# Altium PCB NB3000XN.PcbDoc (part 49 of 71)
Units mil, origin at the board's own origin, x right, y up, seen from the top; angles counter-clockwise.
Board outline 9527.56 x 6929.77 mil, 6 copper layers (Top Layer, GND+SHIELD, MidLayer1, MidLayer2, P2 - 3V3+5V0, Bottom Layer), stack 62.375 mil thick; 832 components, 1027 nets, 4655 pads, 4981 vias.
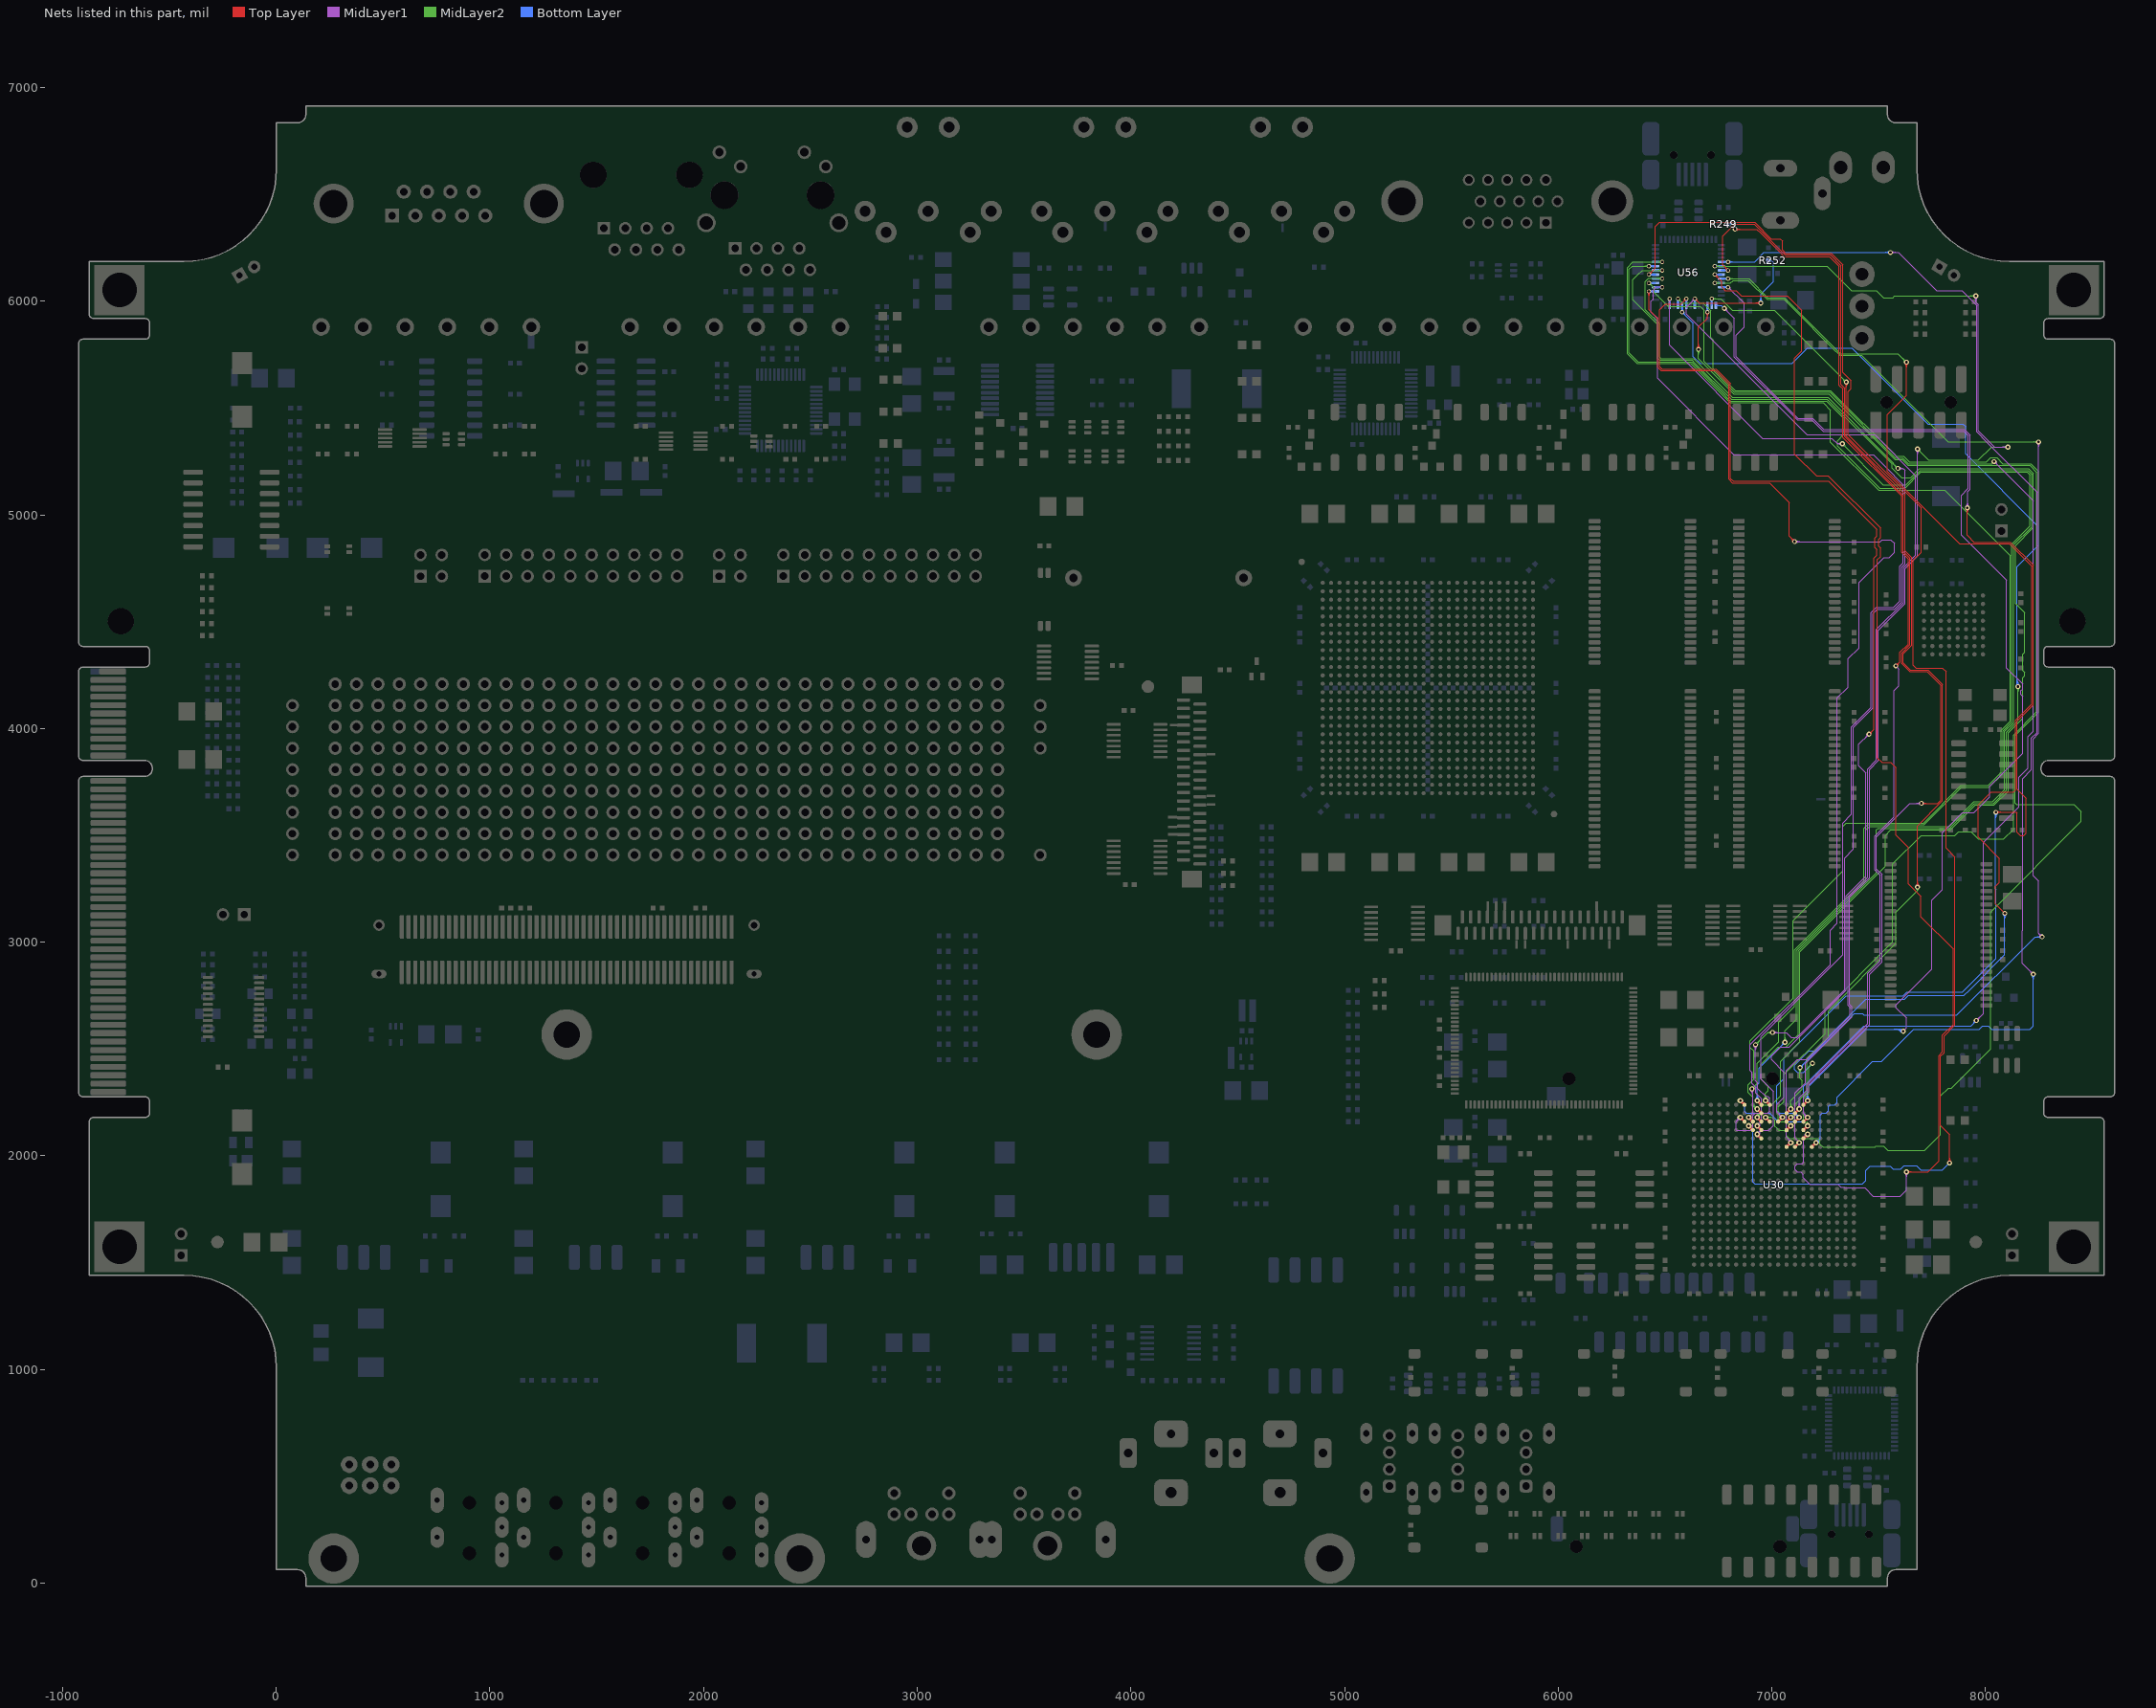
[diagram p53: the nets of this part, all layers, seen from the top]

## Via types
v1: diameter 23, hole 11.81, Top Layer to Bottom Layer, 3672 vias
v2: diameter 26, hole 11.81, Top Layer to Bottom Layer, 461 vias
v3: diameter 19, hole 11.81, Top Layer to Bottom Layer, tented both sides, 396 vias
v4: diameter 23.62, hole 11.81, Top Layer to Bottom Layer, 288 vias
v5: diameter 20, hole 11.81, Top Layer to Bottom Layer, 91 vias
v6: diameter 23, hole 11.81, Top Layer to Bottom Layer, tented both sides, 50 vias
v7: diameter 31, hole 11.81, Top Layer to Bottom Layer, 15 vias
v8: diameter 27.56, hole 11.81, Top Layer to Bottom Layer, tented both sides, 4 vias
v9: diameter 29, hole 11.81, Top Layer to Bottom Layer, 3 vias
v10: diameter 21, hole 11.81, Top Layer to Bottom Layer, 1 vias

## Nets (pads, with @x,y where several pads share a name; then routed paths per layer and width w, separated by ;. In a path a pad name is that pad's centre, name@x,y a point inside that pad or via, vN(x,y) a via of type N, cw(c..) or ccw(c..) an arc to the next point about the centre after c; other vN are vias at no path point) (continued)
HOST_USB.D1: U30.F6 U56.19 | length 6639.8
  Top Layer w8: U30.F6@7187.17,2042.17 v2(7206.85,2061.85) ; U30.F6@7187.17,2048.01 ccw(c7187.17,2062.11) 7197.14,2052.14 ccw(c7207.11,2042.17) U30.F6@7193.01,2042.17 ; v2@7197.85,2061.85 cw(c7176.12,2061.85) 7191.49,2046.49 cw(c7206.85,2031.12) v2@7206.85,2052.85
  MidLayer1 w4: v1(7554.86,6228.37) 7592.21,6228.37 7770.54,6050.04 7889.61,6050.04 7958.81,5980.84 7958.81,5388.73 8004.44,5343.11 8240.52,5107.02 8240.52,3980.73 8215.19,3955.39 8215.19,3808.37 8173.52,3766.71 8173.52,3055 ; v1@7558.75,6224.49 cw(c7568.14,6215.1) 7568.14,6228.37 cw(c7568.14,6241.65) v1@7558.75,6232.26 ; v1@7561.57,6221.66 cw(c7577.79,6205.44) 7577.79,6228.37 cw(c7577.79,6251.31) v1@7561.57,6235.09 ; 8175,3055 8173.19,3053.19 8173.19,2900.37 v1(8223.52,2850.04) ; v1@8214.02,2850.04 ccw(c8191.09,2850.04) 8207.31,2866.26 ccw(c8223.52,2882.48) v1@8223.52,2859.54 ; v1@8218.02,2850.04 ccw(c8204.75,2850.04) 8214.14,2859.43 ccw(c8223.52,2868.82) v1@8223.52,2855.54
  Bottom Layer w4: v5(6795.66,6184.21) 6919.36,6184.21 6963.52,6228.37 v1(7554.86,6228.37) ; v5@6801.32,6178.56 cw(c6814.97,6164.9) 6814.97,6184.21 cw(c6814.98,6203.53) v5@6801.32,6189.87 ; v2(7206.85,2061.85) 7206.85,2069.37 7214.38,2069.37 7227.19,2082.19 7227.19,2191.71 7235.52,2200.04 7254.19,2200.04 7265.52,2211.37 7265.52,2233.37 7271.19,2239.04 7293.86,2239.04 7304.86,2250.04 7304.86,2275.04 7471.52,2441.71 7514.52,2441.71 7664.52,2591.71 7969.52,2591.71 7986.19,2608.37 8012.86,2608.37 8029.52,2591.71 8206.86,2591.71 8223.52,2608.37 v1(8223.52,2850.04) ; v2@7206.85,2068.85 ccw(c7206.85,2085.75) 7218.8,2073.8 ; v2@7206.85,2072.85 ccw(c7206.85,2099.41) 7225.63,2080.63 ccw(c7244.41,2061.85) v2@7217.85,2061.85 ; v2@7213.85,2061.85 cw(c7230.75,2061.85) 7218.8,2073.8 ; v1@7548.14,6221.66 ccw(c7531.92,6205.44) 7531.92,6228.37 ccw(c7531.92,6251.31) v1@7548.14,6235.09 ; v1@7550.97,6224.49 ccw(c7541.58,6215.1) 7541.58,6228.37 ccw(c7541.58,6241.65) v1@7550.97,6232.26 ; v1@8216.81,2843.32 cw(c8200.59,2827.11) 8223.52,2827.11 cw(c8246.46,2827.11) v1@8230.24,2843.32 ; v1@8219.64,2846.15 cw(c8210.25,2836.76) 8223.52,2836.76 cw(c8236.8,2836.76) v1@8227.41,2846.15
  Bottom Layer w8: U56.19@6764.33,6184.21 v5(6795.66,6184.21) ; v5@6791.42,6179.97 ccw(c6781.18,6169.73) 6781.18,6184.21 ccw(c6781.17,6198.7) v5@6791.42,6188.46
HOST_USB.D2: U30.H6 U56.20 | length 6594.3
  Top Layer w8: U30.H6@7108.43,2042.17 v2(7128.11,2061.85) ; U30.H6@7108.43,2048.01 ccw(c7108.43,2062.11) 7118.4,2052.14 ccw(c7128.37,2042.17) U30.H6@7114.27,2042.17 ; v2@7119.11,2061.85 cw(c7097.38,2061.85) 7112.75,2046.49 cw(c7128.11,2031.12) v2@7128.11,2052.85
  MidLayer1 w4: v2(7128.11,2061.85) 7128.11,2058.37 7131.86,2058.37 7131.86,2060.37 7108.86,2083.37 7108.86,2293.71 7156.86,2341.71 7156.86,2433.37 7374.34,2650.86 7374.34,2698.16 7364.52,2707.98 7364.52,3210.08 7456.86,3302.41 7456.86,3808.37 7498.52,3850.04 7498.52,4459.84 7623.86,4585.17 7623.86,4749.77 7681.86,4807.77 v1(7681.86,5308.37) ; v1@7675.14,5301.66 cw(c7658.92,5285.44) 7681.86,5285.44 cw(c7704.79,5285.44) v1@7688.57,5301.66 ; v1@7677.97,5304.49 cw(c7668.58,5295.1) 7681.86,5295.1 cw(c7695.14,5295.1) v1@7685.75,5304.49 ; v4@7948.06,6018.06 cw(c7931.31,6001.31) 7955,6001.31 cw(c7978.69,6001.31) v4@7961.94,6018.06 ; v4@7950.89,6020.89 cw(c7940.97,6010.97) 7955,6010.97 cw(c7969.03,6010.97) v4@7959.11,6020.89 ; v4(7955,6025) 7955,5995.96 7966.81,5984.15 7966.81,5393.19 8042.19,5317.81 v4(8105,5317.81) ; v4@8098.06,5310.87 ccw(c8081.31,5294.13) 8081.31,5317.81 ccw(c8081.31,5341.5) v4@8098.06,5324.75 ; v4@8100.89,5313.7 ccw(c8090.97,5303.78) 8090.97,5317.81 ccw(c8090.97,5331.84) v4@8100.89,5321.92
  MidLayer2 w4: v5(6733,6164.53) 7259.04,6164.53 7373.52,6050.04 7490.19,6050.04 7523.04,6017.19 7567.19,6017.19 7575,6025 v4(7955,6025) ; v5@6738.66,6158.87 cw(c6752.31,6145.21) 6752.31,6164.53 cw(c6752.31,6183.84) v5@6738.66,6170.18 ; v1@7681.86,5298.87 cw(c7681.86,5275.94) 7698.07,5292.16 cw(c7714.29,5308.37) v1@7691.36,5308.37 ; v1@7681.86,5302.87 cw(c7681.86,5289.6) 7691.25,5298.99 cw(c7700.64,5308.37) v1@7687.36,5308.37 ; v1(7681.86,5308.37) 7734.23,5256 7966,5256 8027.81,5317.81 v4(8105,5317.81) ; v4@7948.06,6018.06 ccw(c7931.31,6001.31) 7931.31,6025 ccw(c7931.31,6048.69) v4@7948.06,6031.94 ; v4@7950.89,6020.89 ccw(c7940.97,6010.97) 7940.97,6025 ccw(c7940.97,6039.03) v4@7950.89,6029.11 ; v4@8098.06,5310.87 ccw(c8081.31,5294.13) 8081.31,5317.81 ccw(c8081.31,5341.5) v4@8098.06,5324.75 ; v4@8100.89,5313.7 ccw(c8090.97,5303.78) 8090.97,5317.81 ccw(c8090.97,5331.84) v4@8100.89,5321.92
  Bottom Layer w8: v5(6733,6164.53) U56.20@6764.33,6164.53 ; v5@6737.24,6160.28 cw(c6747.49,6150.04) 6747.49,6164.53 cw(c6747.49,6179.01) v5@6737.24,6168.77
HOST_USB.D3: U30.G3 U56.21 | length 5809.5
  Top Layer w4: 6782.01,6158.5 cw(c6768.35,6144.84) v5@6787.66,6144.84 ; 6782,6158.5 ccw(c6795.66,6172.16) v5@6795.66,6152.84 ; v5(6795.66,6144.84) 6770,6170.5 6770,6304.85 6825.19,6360.04 6917.84,6360.04 7061.17,6216.71 7273.52,6216.71 7323.52,6166.71 7323.52,5610 7340.52,5593 7340.52,5366.37 7363.05,5343.85 7615.19,5091.71 7615.19,4828.37 7646.52,4797.04 7646.52,4392.69 7606.86,4353.02 7606.86,4305 7644.86,4267 7726.69,4267 7791.19,4202.5 7791.19,3665.33 7775.86,3650 v1(7700,3650) ; v1@7703.89,3646.11 cw(c7713.28,3636.72) 7713.28,3650 cw(c7713.28,3663.28) v1@7703.89,3653.89 ; v1@7706.72,3643.28 cw(c7722.94,3627.06) 7722.94,3650 cw(c7722.94,3672.93) v1@7706.72,3656.72
  Top Layer w8: U30.G3@7147.8,2160.28 v2(7167.48,2179.96) ; U30.G3@7147.8,2166.12 ccw(c7147.8,2180.22) 7157.77,2170.25 ccw(c7167.74,2160.28) U30.G3@7153.64,2160.28 ; v2@7158.48,2179.96 cw(c7136.75,2179.96) 7152.12,2164.6 cw(c7167.48,2149.23) v2@7167.48,2170.96
  MidLayer1 w4: v2@7156.48,2179.96 ccw(c7129.92,2179.96) 7148.7,2198.74 ccw(c7167.48,2217.52) v2@7167.48,2190.96 ; v2@7160.48,2179.96 ccw(c7143.58,2179.96) 7155.53,2191.91 ccw(c7167.48,2203.86) v2@7167.48,2186.96 ; v2(7167.48,2179.96) 7148.19,2199.25 7148.19,2275.37 7173.19,2300.37 7173.19,2331.67 7457.19,2615.67 7457.19,2850.37 7515.19,2908.37 7515.19,3316.71 7490.19,3341.71 7490.19,3493.33 7646.86,3650 v1(7700,3650) ; v1@7693.28,3643.28 ccw(c7677.06,3627.06) 7677.06,3650 ccw(c7677.06,3672.93) v1@7693.28,3656.72 ; v1@7696.11,3646.11 ccw(c7686.72,3636.72) 7686.72,3650 ccw(c7686.72,3663.28) v1@7696.11,3653.89
  Bottom Layer w8: U56.21@6764.33,6144.84 v5(6795.66,6144.84) ; v5@6791.42,6140.6 ccw(c6781.18,6130.36) 6781.18,6144.84 ccw(c6781.18,6159.33) v5@6791.42,6149.09
HOST_USB.D4: U30.G5 U56.22 | length 6301.8
  Top Layer w4: v5@6733,6117.16 cw(c6733,6097.84) 6746.66,6111.5 cw(c6760.31,6125.16) v5@6741,6125.16 ; v5(6733,6125.16) 6765.19,6092.97 6765.19,6066.71 6781.86,6050.04 6831.86,6050.04 6856.86,6025.04 7073.52,6025.04 7140.19,5958.37 7140.19,5767.14 7106.52,5733.48 7106.52,5284.79 7208.27,5183.04 7263.15,5183.04 7508.19,4938 7508.19,4894.69 7499.19,4885.69 7499.19,4854.31 7508.19,4845.31 7508.19,4804.41 7494.19,4790.41 7494.19,3862.71 7515.19,3841.71 7556.86,3841.71 7581.86,3816.71 7581.86,3501.02 7640.19,3442.69 7640.19,3273.37 7698.19,3215.37 7698.19,3119 7849.19,2968 7849.19,2615 7798.52,2564.34 7798.52,2486.36 7781.86,2469.69 7781.86,1976.86 7730,1925 v1(7630,1925) ; v1@7633.89,1921.11 cw(c7643.28,1911.72) 7643.28,1925 cw(c7643.28,1938.28) v1@7633.89,1928.89 ; v1@7636.72,1918.28 cw(c7652.94,1902.06) 7652.94,1925 cw(c7652.94,1947.93) v1@7636.72,1931.72
  Top Layer w8: U30.G5@7147.8,2081.54 v2(7167.48,2101.22) ; U30.G5@7147.8,2087.38 ccw(c7147.8,2101.48) 7157.77,2091.51 ccw(c7167.74,2081.54) U30.G5@7153.64,2081.54 ; v2@7158.48,2101.22 cw(c7136.75,2101.22) 7152.12,2085.86 cw(c7167.48,2070.49) v2@7167.48,2092.22
  MidLayer1 w4: v2@7156.48,2101.22 cw(c7129.92,2101.22) 7148.7,2082.44 cw(c7167.48,2063.67) v2@7167.48,2090.22 ; v2@7160.48,2101.22 cw(c7143.58,2101.22) 7155.53,2089.27 cw(c7167.48,2077.32) v2@7167.48,2094.22 ; v2(7167.48,2101.22) 7148.19,2081.93 7148.19,1969.5 7141.43,1962.74 7120.24,1962.74 7109.11,1951.61 7109.11,1935.87 7120.24,1924.74 7134.61,1924.74 7147.11,1912.24 7147.11,1897.87 7177.78,1867.2 7309.34,1867.2 7323.92,1852.63 7336.14,1852.63 7338.56,1850.21 7435,1850.21 7473.71,1811.5 7601.69,1811.5 7630,1839.81 v1(7630,1925) ; v1@7623.28,1918.28 cw(c7607.06,1902.06) 7630,1902.06 cw(c7652.94,1902.06) v1@7636.72,1918.28 ; v1@7626.11,1921.11 cw(c7616.72,1911.72) 7630,1911.72 cw(c7643.28,1911.72) v1@7633.89,1921.11
  Bottom Layer w8: v5(6733,6125.16) U56.22@6764.33,6125.16 ; v5@6737.24,6120.91 cw(c6747.49,6110.67) 6747.49,6125.16 cw(c6747.49,6139.64) v5@6737.24,6129.4
HOST_USB.D5: U30.G4 U56.23 | length 6588.5
  Top Layer w4: v1@7623.28,5708.28 cw(c7607.06,5692.06) 7630,5692.06 cw(c7652.94,5692.06) v1@7636.72,5708.28 ; v1@7626.11,5711.11 cw(c7616.72,5701.72) 7630,5701.72 cw(c7643.28,5701.72) v1@7633.89,5711.11 ; v1(7630,5715) 7630,5560 7540,5470 7540,5203.46 7878.46,4865 8111.02,4865 8216.02,4760 8216.02,4114.05 8140,4038.03 8140,4010 ; v1(8090.19,3135.37) 8047.5,3178.06 8047.5,3262.25 8065.19,3279.94 8065.19,3391.71 7965.19,3491.71 7965.19,3641.71 8027.19,3703.71 8132.52,3703.71 8140.19,3711.37 8140.19,4010
  Top Layer w8: U30.G4@7147.8,2120.91 v2(7167.48,2140.59) ; U30.G4@7147.8,2126.75 ccw(c7147.8,2140.85) 7157.77,2130.88 ccw(c7167.74,2120.91) U30.G4@7153.64,2120.91 ; v2@7158.48,2140.59 cw(c7136.75,2140.59) 7152.12,2125.23 cw(c7167.48,2109.86) v2@7167.48,2131.59
  MidLayer2 w4: v5(6795.66,6105.47) 6845,6105.47 6893.09,6105.47 6981.86,6016.71 7059.84,6016.71 7321.54,5755 7590,5755 v1(7630,5715) ; v5@6801.32,6099.82 cw(c6814.97,6086.16) 6814.97,6105.47 cw(c6814.98,6124.79) v5@6801.32,6111.13 ; 7163.45,2158.41 cw(c7154.44,2149.4) v2@7164.99,2142.27 ; 7166.87,2154.98 cw(c7158.53,2146.64) v2@7168.31,2140.03 ; v2(7167.48,2140.59) 7167.48,2154.37 7163.48,2158.37 7156.52,2158.37 7148.19,2166.71 7148.19,2266.37 7173.52,2291.71 7173.52,2416.71 v1(7190.19,2433.37) ; v1@7180.69,2433.37 cw(c7157.76,2433.37) 7173.97,2417.16 cw(c7190.19,2400.94) v1@7190.19,2423.87 ; v1@7184.69,2433.37 cw(c7171.41,2433.37) 7180.8,2423.99 cw(c7190.19,2414.6) v1@7190.19,2427.87 ; v1@7620.5,5715 ccw(c7597.56,5715) 7613.78,5731.22 ccw(c7630,5747.43) v1@7630,5724.5 ; v1@7624.5,5715 ccw(c7611.22,5715) 7620.61,5724.39 ccw(c7630,5733.78) v1@7630,5720.5
  Bottom Layer w4: v1@7180.69,2433.37 cw(c7157.76,2433.37) 7173.97,2417.16 cw(c7190.19,2400.94) v1@7190.19,2423.87 ; v1@7184.69,2433.37 cw(c7171.41,2433.37) 7180.8,2423.99 cw(c7190.19,2414.6) v1@7190.19,2427.87 ; v1(7190.19,2433.37) 7148.52,2391.71 7118.52,2391.71 7106.86,2403.37 7106.86,2425.04 7173.52,2491.71 7198.52,2491.71 7440.19,2733.37 7621.15,2733.37 7638.48,2750.71 7899.19,2750.71 7925.26,2776.78 8090.19,2941.71 v1(8090.19,3135.37) ; v1@8083.47,3128.66 cw(c8067.26,3112.44) 8090.19,3112.44 cw(c8113.13,3112.44) v1@8096.91,3128.66 ; v1@8086.3,3131.49 cw(c8076.91,3122.1) 8090.19,3122.1 cw(c8103.47,3122.1) v1@8094.08,3131.49
  Bottom Layer w8: U56.23@6764.33,6105.47 v5(6795.66,6105.47) ; v5@6791.42,6101.23 ccw(c6781.18,6090.99) 6781.18,6105.47 ccw(c6781.18,6119.96) v5@6791.42,6109.72
HOST_USB.D6: U30.J2 U56.24 | length 6369.9
  Top Layer w8: U30.J2@7069.06,2199.65 v2(7088.74,2219.33) ; U30.J2@7069.06,2205.49 ccw(c7069.06,2219.59) 7079.03,2209.62 ccw(c7089,2199.65) U30.J2@7074.9,2199.65 ; v2@7079.74,2219.33 cw(c7058.01,2219.33) 7073.38,2203.97 cw(c7088.74,2188.6) v2@7088.74,2210.33
  MidLayer1 w4: v1@8241.81,5334.99 cw(c8225.59,5318.77) 8248.52,5318.77 cw(c8271.46,5318.77) v1@8255.24,5334.99 ; v1@8244.64,5337.82 cw(c8235.25,5328.43) 8248.52,5328.43 cw(c8261.8,5328.43) v1@8252.41,5337.82 ; v1(8248.52,5341.71) 8248.52,3977.41 8223.52,3952.41 8223.52,3311.35 8248.19,3286.69 8248.19,3042.04 v1(8265.19,3025.04) ; v1@8255.69,3025.04 ccw(c8232.76,3025.04) 8248.97,3041.26 ccw(c8265.19,3057.48) v1@8265.19,3034.54 ; v1@8259.69,3025.04 ccw(c8246.41,3025.04) 8255.8,3034.43 ccw(c8265.19,3043.82) v1@8265.19,3030.54
  MidLayer2 w4: v5(6733,6085.79) 6806.86,6085.79 6818.54,6097.47 6889.78,6097.47 6978.54,6008.71 7056.52,6008.71 7098.52,5966.71 7283.03,5782.2 7318.23,5747 7419.23,5747 7790.81,5375.42 7824.52,5341.71 v1(8248.52,5341.71) ; v5@6738.66,6080.13 cw(c6752.31,6066.47) 6752.31,6085.79 cw(c6752.31,6105.1) v5@6738.66,6091.44 ; v2@7080.96,2227.11 ccw(c7062.18,2245.89) 7088.74,2245.89 ccw(c7115.3,2245.89) v2@7096.52,2227.11 ; v2@7083.79,2224.28 ccw(c7071.84,2236.23) 7088.74,2236.23 ccw(c7105.64,2236.23) v2@7093.69,2224.28 ; v2(7088.74,2219.33) 7088.74,2258.37 7142.5,2312.13 7142.5,2352.25 7131.86,2362.89 v1(7131.86,2413.04) ; v1@7125.14,2406.32 cw(c7108.92,2390.11) 7131.86,2390.11 cw(c7154.79,2390.11) v1@7138.57,2406.32 ; v1@7127.97,2409.15 cw(c7118.58,2399.76) 7131.86,2399.76 cw(c7145.14,2399.76) v1@7135.75,2409.15 ; v1@8241.81,5334.99 ccw(c8225.59,5318.77) 8225.59,5341.71 ccw(c8225.59,5364.64) v1@8241.81,5348.43 ; v1@8244.64,5337.82 ccw(c8235.25,5328.43) 8235.25,5341.71 ccw(c8235.25,5354.99) v1@8244.64,5345.6
  Bottom Layer w4: v1(7131.86,2413.04) 7385.52,2666.71 7423.52,2666.71 7431.86,2658.37 7865.19,2658.37 8231.86,3025.04 v1(8265.19,3025.04) ; v1@7131.86,2418.54 ccw(c7131.86,2431.82) 7141.25,2422.43 ccw(c7150.64,2413.04) v1@7137.36,2413.04 ; v1@7131.86,2422.54 ccw(c7131.86,2445.48) 7148.07,2429.26 ccw(c7164.29,2413.04) v1@7141.36,2413.04 ; v1@8258.47,3018.32 ccw(c8242.26,3002.11) 8242.26,3025.04 ccw(c8242.26,3047.98) v1@8258.47,3031.76 ; v1@8261.3,3021.15 ccw(c8251.91,3011.76) 8251.91,3025.04 ccw(c8251.91,3038.32) v1@8261.3,3028.93
  Bottom Layer w8: v5(6733,6085.79) U56.24@6764.33,6085.79 ; v5@6737.24,6081.54 cw(c6747.49,6071.3) 6747.49,6085.79 cw(c6747.49,6100.27) v5@6737.24,6090.03
HOST_USB.D7: U30.H3 U56.25 | length 6707
  Top Layer w4: v1@7908.47,5026.66 cw(c7892.26,5010.44) 7915.19,5010.44 cw(c7938.13,5010.44) v1@7921.91,5026.66 ; v1@7911.3,5029.49 cw(c7901.91,5020.1) 7915.19,5020.1 cw(c7928.47,5020.1) v1@7919.08,5029.49 ; v1(7915.19,5033.37) 7915.19,4904.81 7947,4873 8117,4873 8224.02,4765.98 8224.02,4110.74 8148.19,4034.91 8148.19,3715.5 8190.19,3673.5 8190.19,3511.37 8178.86,3500.04 8162.19,3500.04 8148.52,3513.71 8148.52,3604.37 8144.52,3608.37 v1(8048.52,3608.37) ; v1@8052.41,3604.49 cw(c8061.8,3595.1) 8061.8,3608.37 cw(c8061.8,3621.65) v1@8052.41,3612.26 ; v1@8055.24,3601.66 cw(c8071.46,3585.44) 8071.46,3608.37 cw(c8071.46,3631.31) v1@8055.24,3615.09
  Top Layer w8: U30.H3@7108.43,2160.28 v2(7128.11,2179.96) ; U30.H3@7108.43,2166.12 ccw(c7108.43,2180.22) 7118.4,2170.25 ccw(c7128.37,2160.28) U30.H3@7114.27,2160.28 ; v2@7119.11,2179.96 cw(c7097.38,2179.96) 7112.75,2164.6 cw(c7128.11,2149.23) v2@7128.11,2170.96
  MidLayer1 w4: v5@6795.66,6058.1 cw(c6795.66,6038.79) 6809.32,6052.45 cw(c6822.98,6066.1) v5@6803.66,6066.1 ; v5(6795.66,6066.1) 6866.32,5995.45 6870,5991.76 6870,5879 6833,5842 6833,5741.17 7121.82,5452.35 7190.86,5452.35 7243.17,5400.04 7902.25,5400.04 7928,5374.29 7928,5120.6 7916.36,5108.96 7916.36,5034.54 v1(7915.19,5033.37) ; v1@7908.47,5040.09 ccw(c7889.44,5059.13) 7916.36,5059.13 ; v1@7911.3,5037.26 ccw(c7899.09,5049.47) 7916.36,5049.47 ; 7916.36,5053.49 ccw(c7935.31,5053.49) v1@7921.91,5040.09
  Bottom Layer w4: v2@7117.11,2179.96 ccw(c7090.55,2179.96) 7109.33,2198.74 ccw(c7128.11,2217.52) v2@7128.11,2190.96 ; v2@7121.11,2179.96 ccw(c7104.21,2179.96) 7116.16,2191.91 ccw(c7128.11,2203.86) v2@7128.11,2186.96 ; v2(7128.11,2179.96) 7108.03,2200.04 7031.86,2200.04 7023.52,2208.37 7023.52,2329.04 7056.86,2362.37 7056.86,2458.37 7348.52,2750.04 7615.19,2750.04 7631.86,2766.71 7892.56,2766.71 8048.52,2922.67 8048.52,3246.73 8047.5,3247.75 8047.5,3607.35 v1(8048.52,3608.37) ; v1@8041.81,3601.66 cw(c8028.06,3587.91) 8047.5,3587.91 ; 8047.5,3582.97 cw(c8073.93,3582.97) v1@8055.24,3601.66 ; 8047.5,3592.62 cw(c8064.27,3592.62) v1@8052.41,3604.49
  Bottom Layer w8: U56.25@6764.33,6066.1 v5(6795.66,6066.1) ; v5@6791.42,6061.86 ccw(c6781.18,6051.62) 6781.18,6066.1 ccw(c6781.18,6080.59) v5@6791.42,6070.34
HOST_USB.D8: U30.P3 U56.45 | length 5759
  Top Layer w4: v5@6418.68,6040.76 cw(c6405.02,6027.1) 6424.34,6027.1 cw(c6443.65,6027.1) v5@6430,6040.76 ; v5@6423.52,6046.42 v5(6424.34,6046.42) 6424.34,5960.85 6465.19,5920 6465.19,5691.71 6481.86,5675.04 6735.5,5675.04 6785.27,5625.27 ; 6785,5625 6798.52,5611.48 6798.52,5166.71 6815.19,5150.04 6990.19,5150.04 7081.86,5058.37 7081.86,4900.04 v1(7106.86,4875.04) ; v1@7097.36,4875.04 ccw(c7074.42,4875.04) 7090.64,4891.26 ccw(c7106.86,4907.48) v1@7106.86,4884.54 ; v1@7101.36,4875.04 ccw(c7088.08,4875.04) 7097.47,4884.43 ccw(c7106.86,4893.82) v1@7106.86,4880.54
  Top Layer w8: v2@6852.52,2170.96 cw(c6852.52,2149.23) 6867.88,2164.6 cw(c6883.25,2179.96) v2@6861.52,2179.96 ; v2(6852.52,2179.96) U30.P3@6872.2,2160.28 ; U30.P3@6866.36,2160.28 ccw(c6852.26,2160.28) 6862.23,2170.25 ccw(c6872.2,2180.22) U30.P3@6872.2,2166.12
  MidLayer1 w4: v2@6841.52,2179.96 cw(c6814.96,2179.96) 6833.74,2161.18 cw(c6852.52,2142.4) v2@6852.52,2168.96 ; v2@6845.52,2179.96 cw(c6828.62,2179.96) 6840.57,2168.01 cw(c6852.52,2156.06) v2@6852.52,2172.96 ; v2(6852.52,2179.96) 6833.19,2160.63 6833.19,2122.37 6835.19,2120.37 6899.19,2120.37 6912.19,2133.37 6912.19,2188.71 6923.52,2200.04 6942.19,2200.04 6950.52,2208.37 6950.52,2267.37 6924.52,2293.37 6924.52,2321.71 6906.86,2339.37 6906.86,2391.71 6898.52,2400.04 6898.52,2519.69 7273.52,2894.69 7273.52,3055.39 7306.52,3088.39 7306.52,4143.39 7356.86,4193.73 7356.86,4326.86 7407.86,4377.86 7407.86,4683.37 7524.52,4800.04 7548.52,4800.04 7573.52,4825.04 7573.52,4866.48 7557.19,4882.81 7514.96,4882.81 7507.19,4875.04 v1(7106.86,4875.04) ; v1@7110.75,4871.15 cw(c7120.14,4861.76) 7120.14,4875.04 cw(c7120.14,4888.32) v1@7110.75,4878.93 ; v1@7113.57,4868.32 cw(c7129.79,4852.11) 7129.79,4875.04 cw(c7129.79,4897.98) v1@7113.57,4881.76
  Bottom Layer w8: v5(6424.34,6046.42) U56.45@6455.67,6046.42 ; v5@6428.58,6042.17 cw(c6438.82,6031.93) 6438.82,6046.42 cw(c6438.82,6060.9) v5@6428.58,6050.66
HOST_USB.D9: U30.M5 U56.46 | length 5520.1
  Top Layer w8: v2@6931.26,2092.22 cw(c6931.26,2070.49) 6946.62,2085.86 cw(c6961.99,2101.22) v2@6940.26,2101.22 ; v2(6931.26,2101.22) U30.M5@6950.94,2081.54 ; U30.M5@6945.1,2081.54 ccw(c6931,2081.54) 6940.97,2091.51 ccw(c6950.94,2101.48) U30.M5@6950.94,2087.38
  MidLayer1 w4: 6466.22,6066.71 cw(c6466.22,6045.33) v5@6481.34,6060.45 ; 6469.15,6066.71 ccw(c6469.15,6083.95) v5@6481.34,6071.76 ; 6475.88,6066.71 cw(c6475.88,6054.98) v5@6484.17,6063.27 ; v5(6487,6066.1) 6481.86,6066.1 6481.86,6066.71 6460,6066.71 6445,6051.71 6445,6010 6435,6000 6435,5950 6465,5920 6465,5638.92 6821.92,5282 7474.9,5282 7529.71,5227.19 7615.19,5141.71 7615.19,4775.04 7599.86,4759.71 7599.86,4596.02 7570.54,4566.71 7490.19,4566.71 7465.19,4541.71 7465.19,4099.37 7373.52,4007.71 7373.52,3600.04 7331.86,3558.37 7331.86,2941.71 6948.52,2558.37 6948.52,2358.37 7006.86,2300.04 7006.86,2141.71 6985.52,2120.37 6950.41,2120.37 v2(6931.26,2101.22) ; v2@6931.26,2108.22 ccw(c6931.26,2125.12) 6943.21,2113.17 ccw(c6955.16,2101.22) v2@6938.26,2101.22 ; v2@6931.26,2112.22 ccw(c6931.26,2138.78) 6950.04,2120 ccw(c6968.82,2101.22) v2@6942.26,2101.22
  Bottom Layer w8: U56.46@6455.67,6066.1 v5(6487,6066.1) ; v5@6482.76,6061.86 ccw(c6472.51,6051.62) 6472.51,6066.1 ccw(c6472.51,6080.59) v5@6482.76,6070.35
HOST_USB.D10: U30.P1 U56.47 | length 6788.8
  Top Layer w8: v2@6852.52,2249.7 cw(c6852.52,2227.97) 6867.88,2243.34 cw(c6883.25,2258.7) v2@6861.52,2258.7 ; v2(6852.52,2258.7) U30.P1@6872.2,2239.02 ; U30.P1@6866.36,2239.02 ccw(c6852.26,2239.02) 6862.23,2248.99 ccw(c6872.2,2258.96) U30.P1@6872.2,2244.86
  MidLayer1 w4: v1(7956.86,2633.37) 7989.86,2666.37 7989.86,3466.37 7998.52,3475.04 8156.86,3633.37 8156.86,3773.17 8199.19,3815.5 8199.19,3962.02 8224.52,3987.35 8224.52,5065.71 v1(8040.19,5250.04) ; v1@7956.86,2638.87 ccw(c7956.86,2652.15) 7966.25,2642.76 ccw(c7975.64,2633.37) v1@7962.36,2633.37 ; v1@7956.86,2642.87 ccw(c7956.86,2665.81) 7973.07,2649.59 ccw(c7989.29,2633.37) v1@7966.36,2633.37 ; v1@8040.19,5240.54 cw(c8040.19,5217.61) 8056.41,5233.82 cw(c8072.63,5250.04) v1@8049.69,5250.04 ; v1@8040.19,5244.54 cw(c8040.19,5231.26) 8049.58,5240.65 cw(c8058.97,5250.04) v1@8045.69,5250.04
  MidLayer2 w4: v5@6424.34,6077.79 cw(c6424.34,6058.47) 6438,6072.13 cw(c6451.65,6085.79) v5@6432.34,6085.79 ; v5(6424.34,6085.79) 6450.14,6059.99 6450.14,6040.97 6516.06,5975.04 6665.19,5975.04 6681.86,5958.37 6681.86,5717.32 6824.8,5574.37 7271.82,5574.37 7579.48,5266.71 7612.82,5266.71 7639.53,5240 8030,5240 v1@8040,5250 ; v1@8040.07,5249.93 v1(8040.19,5250.04)
  Bottom Layer w4: v2@6852.52,2247.7 cw(c6852.52,2221.14) 6871.3,2239.92 cw(c6890.08,2258.7) v2@6863.52,2258.7 ; v2@6852.52,2251.7 cw(c6852.52,2234.8) 6864.47,2246.75 cw(c6876.42,2258.7) v2@6859.52,2258.7 ; v2(6852.52,2258.7) 6872.86,2238.36 6872.86,2208.04 6880.86,2200.04 6989.19,2200.04 7029.52,2159.71 7146.19,2159.71 7148.19,2161.71 7148.19,2324.71 7431.86,2608.37 7931.86,2608.37 v1(7956.86,2633.37) ; v1@7947.36,2633.37 cw(c7924.42,2633.37) 7940.64,2617.16 cw(c7956.86,2600.94) v1@7956.86,2623.87 ; v1@7951.36,2633.37 cw(c7938.08,2633.37) 7947.47,2623.99 cw(c7956.86,2614.6) v1@7956.86,2627.87
  Bottom Layer w8: v5(6424.34,6085.79) U56.47@6455.67,6085.79 ; v5@6428.58,6081.54 cw(c6438.82,6071.3) 6438.82,6085.79 cw(c6438.82,6100.27) v5@6428.58,6090.03
HOST_USB.D11: U30.M4 U56.48 | length 6076.9
  Top Layer w8: v2@6931.26,2131.59 cw(c6931.26,2109.86) 6946.62,2125.23 cw(c6961.99,2140.59) v2@6940.26,2140.59 ; v2(6931.26,2140.59) U30.M4@6950.94,2120.91 ; U30.M4@6945.1,2120.91 ccw(c6931,2120.91) 6940.97,2130.88 ccw(c6950.94,2140.85) U30.M4@6950.94,2126.75
  MidLayer1 w4: v1@6916.81,2512.99 cw(c6900.59,2496.77) 6923.52,2496.77 cw(c6946.46,2496.77) v1@6930.24,2512.99 ; v1@6919.64,2515.82 cw(c6910.25,2506.43) 6923.52,2506.43 cw(c6936.8,2506.43) v1@6927.41,2515.82 ; v1(6923.52,2519.71) 6923.52,2352.71 6934.52,2341.71 6934.52,2314.04 6970.86,2277.71 6981.86,2277.71 6990.19,2269.37 6990.19,2208.37 6981.86,2200.04 6955.86,2200.04 6950.86,2195.04 6950.86,2160.71 6931.26,2141.11 v2(6931.26,2140.59) ; v2@6931.26,2147.59 ccw(c6931.26,2163.23) 6942.32,2152.17 ; v2@6931.26,2151.59 ccw(c6931.26,2176.89) 6949.15,2159 ; v2@6938.26,2140.59 cw(c6956.41,2140.59) 6943.58,2153.43 ; v2@6942.26,2140.59 cw(c6970.07,2140.59) 6950.41,2160.26 ; v1(7003.19,2577.37) 7067.63,2577.37 7090,2555 7117.17,2555 7340.19,2778.02 7340.19,3395 7381.86,3436.67 7381.86,4004.73 7473.52,4096.39 7473.52,4538.73 7493.5,4558.71 7573.86,4558.71 7607.86,4592.71 7607.86,4756.39 7623.52,4772.06 7623.52,5209.18 7615,5217.71 v1(7590.19,5217.71) ; v1@7007.08,2573.49 cw(c7016.47,2564.1) 7016.47,2577.37 cw(c7016.47,2590.65) v1@7007.08,2581.26 ; v1@7009.91,2570.66 cw(c7026.13,2554.44) 7026.13,2577.37 cw(c7026.13,2600.31) v1@7009.91,2584.09 ; v1@7594.08,5213.82 cw(c7603.47,5204.43) 7603.47,5217.71 cw(c7603.47,5230.99) v1@7594.08,5221.6 ; v1@7596.91,5210.99 cw(c7613.13,5194.77) 7613.13,5217.71 cw(c7613.13,5240.64) v1@7596.91,5224.43
  MidLayer2 w4: 6460.68,6108.37 cw(c6460.68,6079.15) v5@6481.34,6099.82 ; 6470.34,6108.37 cw(c6470.34,6088.81) v5@6484.17,6102.64 ; 6474.69,6108.37 ccw(c6474.69,6117.78) v5@6481.34,6111.13 ; v5(6487,6105.47) 6481.86,6105.47 6481.86,6108.37 6423.52,6108.37 6406.86,6091.71 6406.86,5961.36 6473.52,5894.69 6473.52,5737.79 6478.94,5732.37 6632.86,5732.37 6664.64,5700.59 6815.19,5550.04 7262.21,5550.04 7570.83,5241.42 7570.83,5237.07 v1(7590.19,5217.71) ; v1(6923.52,2519.71) 6981.19,2577.37 ; v1@6923.52,2525.21 ccw(c6923.52,2538.49) 6932.91,2529.1 ccw(c6942.3,2519.71) v1@6929.02,2519.71 ; v1@6923.52,2529.21 ccw(c6923.52,2552.14) 6939.74,2535.93 ccw(c6955.96,2519.71) v1@6933.02,2519.71 ; v1(7003.19,2577.37) 6981.19,2577.37 ; v1@7580.69,5217.71 ccw(c7557.76,5217.71) 7573.97,5233.93 ccw(c7590.19,5250.14) v1@7590.19,5227.21 ; v1@7584.69,5217.71 ccw(c7571.41,5217.71) 7580.8,5227.1 ccw(c7590.19,5236.49) v1@7590.19,5223.21 ; 6981.19,2577.37 cw(c6981.19,2556.66) 6996.27,2570.86 ccw(c6981.19,2556.66) 6981.19,2577.37 ; 6981.19,2577.37 ccw(c6981.19,2598.09) 6996.27,2583.89 cw(c6981.19,2598.09) 6981.19,2577.37 ; 6990.45,2577.37 cw(c6990.45,2565.38) 6999.19,2573.6 ccw(c6990.45,2565.38) 6990.45,2577.37 ; 6990.45,2577.37 ccw(c6990.45,2589.37) 6999.19,2581.15 cw(c6990.45,2589.37) 6990.45,2577.37
  Bottom Layer w8: U56.48@6455.67,6105.47 v5(6487,6105.47) ; v5@6482.76,6101.23 ccw(c6472.51,6090.99) 6472.51,6105.47 ccw(c6472.51,6119.96) v5@6482.76,6109.72
HOST_USB.D12: U30.N4 U56.49 | length 7395.9
  Top Layer w4: v5(6424.34,6125.16) 6455,6155.82 6455,6350 6475,6370 6919.19,6370 6996.69,6292.5 7040,6292.5 7050,6282.5 7050,6239.19 7064.48,6224.71 7277.79,6224.71 7331.52,6170.98 7331.52,5667.04 7370.38,5628.19 7370.38,5590.38 7356.52,5576.52 7356.52,5375.63 7698.52,5033.63 7698.52,4825.04 7662.52,4789.04 7662.52,4296.37 7675.52,4283.37 7798.52,4283.37 7815.19,4266.71 7815.19,3440 7857.19,3398 7857.19,2611.69 7806.86,2561.36 7806.86,2483.37 7790.19,2466.71 7790.19,2141.71 7831.86,2100.04 v1(7831.86,1966.71) ; v5@6424.34,6133.16 ccw(c6424.34,6152.47) 6438,6138.82 ccw(c6451.65,6125.16) v5@6432.34,6125.16 ; v1@7825.14,1973.43 ccw(c7808.92,1989.64) 7831.86,1989.64 ccw(c7854.79,1989.64) v1@7838.57,1973.43 ; v1@7827.97,1970.6 ccw(c7818.58,1979.99) 7831.86,1979.99 ccw(c7845.14,1979.99) v1@7835.75,1970.6
  Top Layer w8: v2@6891.89,2131.59 cw(c6891.89,2109.86) 6907.25,2125.23 cw(c6922.62,2140.59) v2@6900.89,2140.59 ; v2(6891.89,2140.59) U30.N4@6911.57,2120.91 ; U30.N4@6905.73,2120.91 ccw(c6891.63,2120.91) 6901.6,2130.88 ccw(c6911.57,2140.85) U30.N4@6911.57,2126.75
  Bottom Layer w4: v2@6891.89,2129.59 cw(c6891.89,2103.03) 6910.67,2121.81 cw(c6929.44,2140.59) v2@6902.89,2140.59 ; v2@6891.89,2133.59 cw(c6891.89,2116.69) 6903.84,2128.64 cw(c6915.79,2140.59) v2@6898.89,2140.59 ; v2(6891.89,2140.59) 6911.52,2120.96 6911.52,1878.48 6921,1869 7425,1869 7440.02,1884.02 7440.02,1932.58 7459.82,1952.37 7553.94,1952.37 7567.81,1938.5 7602.19,1938.5 7617.9,1954.21 7677.77,1954.21 7697.98,1934 7799.15,1934 v1(7831.86,1966.71)
  Bottom Layer w8: v5(6424.34,6125.16) U56.49@6455.67,6125.16 ; v5@6428.58,6120.91 cw(c6438.82,6110.67) 6438.82,6125.16 cw(c6438.82,6139.64) v5@6428.58,6129.4
HOST_USB.D13: U30.M3 U56.50 | length 6692
  Top Layer w8: v2@6931.26,2170.96 cw(c6931.26,2149.23) 6946.62,2164.6 cw(c6961.99,2179.96) v2@6940.26,2179.96 ; v2(6931.26,2179.96) U30.M3@6950.94,2160.28 ; U30.M3@6945.1,2160.28 ccw(c6931,2160.28) 6940.97,2170.25 ccw(c6950.94,2180.22) U30.M3@6950.94,2166.12
  MidLayer2 w4: v5@6481.34,6139.19 ccw(c6467.69,6125.53) 6467.69,6144.84 ccw(c6467.69,6164.16) v5@6481.34,6150.5 ; v5(6487,6144.84) 6393.33,6144.84 6373.52,6125.04 6350,6101.52 6350,6006.9 6373.52,5983.37 6465.19,5891.71 6465.19,5734.81 6475.63,5724.37 6627.19,5724.37 6636.89,5714.68 6809.86,5541.71 7259.23,5541.71 7562.83,5238.11 7562.83,5219.07 7606.86,5175.04 7650.11,5175.04 7691.07,5216 8201.37,5216 8223.86,5193.52 8223.86,4941.05 8139.86,4857.05 8139.86,4585.33 8182.81,4542.38 8182.81,4356.66 8173.52,4347.37 8173.52,4271.66 8182.81,4262.38 8182.81,4247.62 8173.52,4238.34 8173.52,4047.04 8106.86,3980.37 8106.86,3708.37 8040.19,3641.71 7952.19,3641.71 7835.52,3525.04 7556.86,3525.04 7531.86,3500.04 7531.86,3355.39 7131.86,2955.39 7131.86,2533.37 7040.19,2441.71 7040.19,2281.04 6998.52,2239.37 6962.86,2239.37 6950.52,2227.04 6950.52,2211.37 ; v2@6930.28,2179.75 cw(c6947.37,2183.48) 6935,2195.85 ; v2(6931.26,2179.96) 6931.86,2180.56 6931.86,2192.71 6950.52,2211.37 ; v2@6934.19,2180.6 cw(c6955.86,2185.34) 6940.18,2201.03 ; v2@6938.1,2181.46 cw(c6964.35,2187.2) 6945.35,2206.2 ; v2@6942.01,2182.31 cw(c6972.84,2189.05) 6950.52,2211.37
  Bottom Layer w8: U56.50@6455.67,6144.84 v5(6487,6144.84) ; v5@6482.76,6140.6 ccw(c6472.51,6130.36) 6472.51,6144.84 ccw(c6472.51,6159.33) v5@6482.76,6149.09
HOST_USB.D14: U30.N3 U56.51 | length 6868
  Top Layer w8: v2@6891.89,2170.96 cw(c6891.89,2149.23) 6907.25,2164.6 cw(c6922.62,2179.96) v2@6900.89,2179.96 ; v2(6891.89,2179.96) U30.N3@6911.57,2160.28 ; U30.N3@6905.73,2160.28 ccw(c6891.63,2160.28) 6901.6,2170.25 ccw(c6911.57,2180.22) U30.N3@6911.57,2166.12
  MidLayer1 w4: v2(6891.89,2179.96) 6911.19,2199.26 6911.19,2309.04 v1(6906.86,2313.37) ; v1@6900.14,2306.66 cw(c6873.46,2279.98) 6911.19,2279.98 ; v1@6902.97,2309.49 cw(c6883.12,2289.64) 6911.19,2289.64 ; v1@6905.8,2312.31 cw(c6892.78,2299.29) 6911.19,2299.29 ; 6911.19,2300.9 cw(c6919.33,2300.9) v1@6913.57,2306.66
  MidLayer2 w4: v5@6418.68,6158.87 ccw(c6405.04,6145.23) 6405.04,6164.52 ccw(c6405.01,6183.86) v5@6418.68,6170.18 ; v5@6424.34,6166.71 6424.34,6164.52 6346.34,6164.52 6331.86,6150.04 6331.86,5758.37 6365.19,5725.04 6373.86,5716.37 6623.88,5716.37 6759.26,5580.99 6806.88,5533.37 7256.25,5533.37 7335,5454.62 7335,5375 7306.86,5346.86 7306.86,5322.04 7503.86,5125.04 7622.74,5125.04 7697.7,5200 8194.74,5200 8207.86,5186.89 8207.86,4947.67 8123.52,4863.34 8123.52,4030.98 8081.86,3989.32 8081.86,3791.04 8015.86,3725.04 7887.82,3725.04 7712.82,3550.04 7448.52,3550.04 7431.86,3533.37 7431.86,3289.34 7106.86,2964.34 7106.86,2700.04 7031.86,2625.04 7031.86,2533.37 6931.86,2433.37 6931.86,2338.37 v1(6906.86,2313.37) ; v1@6906.86,2318.87 ccw(c6906.86,2332.15) 6916.25,2322.76 ccw(c6925.64,2313.37) v1@6912.36,2313.37 ; v1@6906.86,2322.87 ccw(c6906.86,2345.81) 6923.07,2329.59 ccw(c6939.29,2313.37) v1@6916.36,2313.37
  Bottom Layer w8: v5(6424.34,6164.53) U56.51@6455.67,6164.53 ; v5@6428.58,6160.28 cw(c6438.82,6150.04) 6438.82,6164.53 cw(c6438.82,6179.01) v5@6428.58,6168.77
HOST_USB.D15: U30.M2 U56.52 | length 6510.9
  Top Layer w8: v2@6931.26,2210.33 cw(c6931.26,2188.6) 6946.62,2203.97 cw(c6961.99,2219.33) v2@6940.26,2219.33 ; v2(6931.26,2219.33) U30.M2@6950.94,2199.65 ; U30.M2@6945.1,2199.65 ccw(c6931,2199.65) 6940.97,2209.62 ccw(c6950.94,2219.59) U30.M2@6950.94,2205.49
  MidLayer2 w4: 6465.66,6183.37 ccw(c6465.66,6205.55) v5@6481.34,6189.87 ; 6469.71,6183.37 cw(c6469.71,6166.92) v5@6481.34,6178.56 ; 6475.32,6183.37 ccw(c6475.32,6195.89) v5@6484.17,6187.04 ; v5@6487,6183.37 6348.52,6183.37 6323.52,6158.37 6323.52,5754.85 6370,5708.37 6620.56,5708.37 6803.9,5525.04 7239.96,5525.04 7275,5490 7275,5340 7500,5115 7808.56,5115 8115.19,4808.37 8115.19,4033.96 8073.52,3992.3 8073.52,3794.02 8012.88,3733.37 7884.84,3733.37 7709.84,3558.37 7348.52,3558.37 7331.86,3541.71 7331.86,3333.37 7098.52,3100.04 7098.52,2737.37 6898.52,2537.37 6898.52,2507.37 6915.19,2490.71 6915.19,2360.04 6888.52,2333.37 6888.52,2297.04 6912.19,2273.37 6912.19,2238.4 v2(6931.26,2219.33) ; v2@6920.26,2219.33 ccw(c6893.7,2219.33) 6912.48,2238.11 ccw(c6931.26,2256.89) v2@6931.26,2230.33 ; v2@6924.26,2219.33 ccw(c6907.36,2219.33) 6919.31,2231.28 ccw(c6931.26,2243.23) v2@6931.26,2226.33
  Bottom Layer w8: U56.52@6455.67,6184.21 v5(6487,6184.21) ; v5@6482.76,6179.97 ccw(c6472.51,6169.73) 6472.51,6184.21 ccw(c6472.52,6198.7) v5@6482.76,6188.46
HOST_USB.FIFOADR0: U30.L1 U56.37 | length 6197.4
  Top Layer w8: v2@6970.63,2249.7 cw(c6970.63,2227.97) 6985.99,2243.34 cw(c7001.36,2258.7) v2@6979.63,2258.7 ; v2(6970.63,2258.7) U30.L1@6990.31,2239.02 ; U30.L1@6984.47,2239.02 ccw(c6970.37,2239.02) 6980.34,2248.99 ccw(c6990.31,2258.96) U30.L1@6990.31,2244.86
  MidLayer2 w4: v2@6962.85,2266.48 ccw(c6944.07,2285.26) 6970.63,2285.26 ccw(c6997.19,2285.26) v2@6978.41,2266.48 ; v2@6965.68,2263.65 ccw(c6953.73,2275.6) 6970.63,2275.6 ccw(c6987.53,2275.6) v2@6975.58,2263.65 ; v2(6970.63,2258.7) 6970.63,2291.89 6983.75,2305 6983.75,2323.15 6948.52,2358.37 6948.52,2427.71 7029.19,2508.37 7065.19,2508.37 7123.52,2566.71 7123.52,2958.37 7490.19,3325.04 7490.19,3525.04 7498.52,3533.37 7832.54,3533.37 7949.21,3650.04 8037.21,3650.04 8098.52,3711.36 8098.52,3983.35 8152.19,4037.02 v1(8152.19,4196.71) ; v1@8145.47,4189.99 cw(c8129.26,4173.77) 8152.19,4173.77 cw(c8175.13,4173.77) v1@8158.91,4189.99 ; v1@8148.3,4192.82 cw(c8138.91,4183.43) 8152.19,4183.43 cw(c8165.47,4183.43) v1@8156.08,4192.82
  Bottom Layer w4: v5@6580.47,5941.34 cw(c6580.47,5922.02) 6594.13,5935.68 cw(c6607.79,5949.34) v5@6588.47,5949.34 ; v5(6580.47,5949.34) 6631.86,5897.95 6631.86,5741.71 6665.19,5708.37 7095.54,5708.37 7167.17,5780 7375.67,5780 7710.33,5445.33 ; 7710,5445 7730,5425 7895,5425 7906.86,5413.14 7906.86,5285.75 8248.69,4943.92 8248.69,4858.69 8147.02,4757.02 8147.02,4201.87 v1(8152.19,4196.71) ; v1@8145.47,4203.43 ccw(c8141.73,4207.17) 8147.02,4207.17 ; 8147.02,4212.8 ccw(c8168.28,4212.8) v1@8153.25,4197.77 ; 8147.02,4222.46 ccw(c8177.94,4222.46) v1@8156.08,4200.6 ; 8147.02,4232.11 ccw(c8187.6,4232.11) v1@8158.91,4203.43
  Bottom Layer w8: v5@6576.23,5953.58 ccw(c6565.99,5963.82) 6580.47,5963.82 ccw(c6594.96,5963.82) v5@6584.72,5953.58 ; v5(6580.47,5949.34) U56.37@6580.47,5980.67
HOST_USB.FIFOADR1: U30.L3 U56.38 | length 7094.5
  Top Layer w8: v2@6970.63,2170.96 cw(c6970.63,2149.23) 6985.99,2164.6 cw(c7001.36,2179.96) v2@6979.63,2179.96 ; v2(6970.63,2179.96) U30.L3@6990.31,2160.28 ; U30.L3@6984.47,2160.28 ccw(c6970.37,2160.28) 6980.34,2170.25 ccw(c6990.31,2180.22) U30.L3@6990.31,2166.12
  MidLayer2 w4: v5@6560.79,6004 cw(c6560.79,5984.69) 6574.44,5998.34 cw(c6588.1,6012) v5@6568.79,6012 ; v5(6560.79,6012) 6581.08,5991.71 6678.84,5991.71 6715.19,5955.36 6715.19,5829.81 6725,5820 6725,5685.49 6828.11,5582.37 7275.13,5582.37 7582.8,5274.71 7616.13,5274.71 7642.84,5248 8005,5248 8025,5268 8053,5268 8081,5240 8211.52,5240 8248.52,5203 8248.52,4076.79 8138.86,3967.12 8138.86,3651.14 8145,3645 8270,3645 8413.52,3645 8448.52,3610 8448.52,3566.71 8023.52,3141.71 8023.52,2500.04 7840.19,2316.71 7826.86,2316.71 7790.19,2280.04 7790.19,2100.04 7715.19,2025.04 7543.19,2025.04 7523.52,2044.71 7487.52,2044.71 7484.52,2041.71 7239.49,2041.71 7225.85,2055.35 7225.85,2069.72 7214.72,2080.85 7082.24,2080.85 7068.37,2094.72 7068.37,2109.09 7057.24,2120.22 7032.01,2120.22 7020.1,2132.14 7015.19,2137.04 7015.19,2166.71 7001.94,2179.96 v2(6970.63,2179.96) ; v2@6975.58,2175.01 cw(c6987.53,2163.06) 6987.53,2179.96 cw(c6987.53,2196.86) v2@6975.58,2184.91 ; v2@6978.41,2172.18 cw(c6997.19,2153.4) 6997.19,2179.96 cw(c6997.19,2206.52) v2@6978.41,2187.74
  Bottom Layer w8: v5@6556.54,6007.76 cw(c6546.3,5997.51) 6560.79,5997.51 cw(c6575.27,5997.51) v5@6565.03,6007.76 ; U56.38@6560.79,5980.67 v5(6560.79,6012)
HOST_USB.FIFOADR2: U30.K3 U56.36 | length 5420.9
  Top Layer w4: v5@6592.16,6012 cw(c6572.84,6012) 6586.5,5998.34 cw(c6600.16,5984.69) v5@6600.16,6004 ; v5(6600.16,6012) 6574.71,5986.55 6555,5986.55 6501.55,5986.55 6475,5960 6475,5693.21 6485.17,5683.04 6738.82,5683.04 6806.86,5615 6806.86,5169.69 6818.5,5158.04 6969.67,5158.04 6970,5158.37 7265.19,5158.37 7491.52,4932.04 7491.52,4900.65 7483.19,4892.32 7483.19,4847.68 7491.52,4839.35 7491.52,4810.37 7478.19,4797.04 7478.19,3997.37 v1(7454.86,3974.04) ; v1@7454.86,3979.54 ccw(c7454.86,3992.82) 7464.25,3983.43 ccw(c7473.64,3974.04) v1@7460.36,3974.04 ; v1@7454.86,3983.54 ccw(c7454.86,4006.48) 7471.07,3990.26 ccw(c7487.29,3974.04) v1@7464.36,3974.04
  Top Layer w8: U30.K3@7029.69,2160.28 v2(7049.37,2179.96) ; U30.K3@7029.69,2166.12 ccw(c7029.69,2180.22) 7039.66,2170.25 ccw(c7049.63,2160.28) U30.K3@7035.53,2160.28 ; v2@7040.37,2179.96 cw(c7018.64,2179.96) 7034.01,2164.6 cw(c7049.37,2149.23) v2@7049.37,2170.96
  MidLayer1 w4: v2@7038.37,2179.96 ccw(c7011.81,2179.96) 7030.59,2198.74 ccw(c7049.37,2217.52) v2@7049.37,2190.96 ; v2@7042.37,2179.96 ccw(c7025.47,2179.96) 7037.42,2191.91 ccw(c7049.37,2203.86) v2@7049.37,2186.96 ; v2(7049.37,2179.96) 7023.52,2205.81 7023.52,2241.71 7056.86,2275.04 7056.86,2391.71 6998.52,2450.04 6998.52,2466.71 7040.19,2508.37 7081.86,2508.37 7348.52,2775.04 7348.52,3216.71 7440.19,3308.37 7440.19,3791.71 7406.86,3825.04 7406.86,3926.04 v1(7454.86,3974.04) ; v1@7445.36,3974.04 cw(c7422.42,3974.04) 7438.64,3957.82 cw(c7454.86,3941.61) v1@7454.86,3964.54 ; v1@7449.36,3974.04 cw(c7436.08,3974.04) 7445.47,3964.65 cw(c7454.86,3955.26) v1@7454.86,3968.54
  Bottom Layer w8: v5@6595.91,6007.76 cw(c6585.67,5997.51) 6600.16,5997.51 cw(c6614.64,5997.51) v5@6604.4,6007.76 ; U56.36@6600.16,5980.67 v5(6600.16,6012)
HOST_USB.FLAGA: U30.G1 U56.29 | length 5735.7
  Top Layer w8: U30.G1@7147.8,2239.02 v2(7167.48,2258.7) ; U30.G1@7147.8,2244.86 ccw(c7147.8,2258.96) 7157.77,2248.99 ccw(c7167.74,2239.02) U30.G1@7153.64,2239.02 ; v2@7158.48,2258.7 cw(c7136.75,2258.7) 7152.12,2243.34 cw(c7167.48,2227.97) v2@7167.48,2249.7
  MidLayer1 w4: v1@6777.52,5957.21 cw(c6777.52,5934.27) 6793.74,5950.49 cw(c6809.96,5966.71) v1@6787.02,5966.71 ; v1@6777.52,5961.21 cw(c6777.52,5947.93) 6786.91,5957.32 cw(c6796.3,5966.71) v1@6783.02,5966.71 ; v1(6777.52,5966.71) 6825,5919.23 6825,5737.86 7118.51,5444.35 7187.55,5444.35 7240.19,5391.71 7899.27,5391.71 7920,5370.98 7920,5123.91 7887.5,5091.41 7887.5,4905.71 8098.52,4694.69 8098.52,4283.37 8173.52,4208.37 8173.52,4185.04 8166.15,4177.66 8166.15,4159.67 8175,4150.82 8175,3884.85 8020,3729.85 8020,3681.57 7945.81,3607.37 7892.37,3607.37 7798.52,3513.52 7798.52,3246.37 7748.52,3196.37 7748.52,2874.43 7581.19,2707.1 7581.19,2693.81 7630,2645 7630,2598.18 v1(7615.19,2583.37)
  Bottom Layer w4: U56.29@6737.95,5980.67 6763.86,5980.67 6777.52,5967 v1(6777.52,5966.71) ; U56.29@6740.78,5977.84 cw(c6747.61,5971.01) 6747.61,5980.67 cw(c6747.61,5990.33) U56.29@6740.78,5983.5 ; v2@7159.7,2266.48 ccw(c7140.92,2285.26) 7167.48,2285.26 ccw(c7194.04,2285.26) v2@7175.26,2266.48 ; v2@7162.53,2263.65 ccw(c7150.58,2275.6) 7167.48,2275.6 ccw(c7184.38,2275.6) v2@7172.43,2263.65 ; v2(7167.48,2258.7) 7167.48,2319 7179.93,2331.45 7440.19,2591.71 7606.86,2591.71 v1(7615.19,2583.37) ; 7572.14,2591.71 cw(c7572.14,2540.32) v1@7608.47,2576.66 ; 7581.79,2591.71 cw(c7581.79,2549.98) v1@7611.3,2579.49 ; 7591.45,2591.71 cw(c7591.45,2559.64) v1@7614.13,2582.31 ; 7601.11,2591.71 cw(c7601.11,2569.29) v1@7616.96,2585.14
HOST_USB.FLAGB: U30.J3 U56.30 | length 5222.6
  Top Layer w4: v1@7341.81,5615.66 cw(c7325.59,5599.44) 7348.52,5599.44 cw(c7371.46,5599.44) v1@7355.24,5615.66 ; v1@7344.64,5618.49 cw(c7335.25,5609.1) 7348.52,5609.1 cw(c7361.8,5609.1) v1@7352.41,5618.49 ; v1(7348.52,5622.37) 7348.52,5370.04 7623.52,5095.04 7623.52,4831.35 7654.52,4800.35 7654.52,4389.37 7615.19,4350.04 7615.19,4307.98 7648.17,4275 7730,4275 7736.48,4268.52 7799.19,4205.81 7799.19,3662.02 7681.86,3544.69 v1(7681.86,3258.04) ; v1@7675.14,3264.76 ccw(c7658.92,3280.98) 7681.86,3280.98 ccw(c7704.79,3280.98) v1@7688.57,3264.76 ; v1@7677.97,3261.93 ccw(c7668.58,3271.32) 7681.86,3271.32 ccw(c7695.14,3271.32) v1@7685.75,3261.93
  Top Layer w8: U30.J3@7069.06,2160.28 v2(7088.74,2179.96) ; U30.J3@7069.06,2166.12 ccw(c7069.06,2180.22) 7079.03,2170.25 ccw(c7089,2160.28) U30.J3@7074.9,2160.28 ; v2@7079.74,2179.96 cw(c7058.01,2179.96) 7073.38,2164.6 cw(c7088.74,2149.23) v2@7088.74,2170.96
  MidLayer2 w4: v5(6718.27,6012) 6761.57,6012 6815.19,5958.37 7012.52,5958.37 v1(7348.52,5622.37) ; v5@6723.92,6006.34 cw(c6737.58,5992.69) 6737.58,6012 cw(c6737.58,6031.31) v5@6723.92,6017.66 ; v2(7088.74,2179.96) 7108.86,2200.08 7108.86,2241.71 7165.19,2298.04 7165.19,2458.37 7264.86,2558.04 7264.86,2678.37 7581.86,2995.37 7581.86,3141.71 7681.86,3241.71 ; v2@7088.74,2186.96 ccw(c7088.74,2203.86) 7100.69,2191.91 ccw(c7112.64,2179.96) v2@7095.74,2179.96 ; v2@7088.74,2190.96 ccw(c7088.74,2217.52) 7107.52,2198.74 ccw(c7126.3,2179.96) v2@7099.74,2179.96 ; v1@7339.02,5622.37 ccw(c7316.09,5622.37) 7332.31,5638.59 ccw(c7348.52,5654.81) v1@7348.52,5631.87 ; v1@7343.02,5622.37 ccw(c7329.75,5622.37) 7339.14,5631.76 ccw(c7348.52,5641.15) v1@7348.52,5627.87 ; v1@7677.16,3249.78 cw(c7672.57,3241.71) 7681.86,3241.71 ; v1(7681.86,3258.04) 7681.86,3241.71 ; v1@7686.55,3249.78 ccw(c7691.15,3241.71) 7681.86,3241.71
  Bottom Layer w8: v5@6714.03,6007.76 cw(c6703.78,5997.51) 6718.27,5997.51 cw(c6732.75,5997.51) v5@6722.51,6007.76 ; U56.30@6718.27,5980.67 v5(6718.27,6012)
HOST_USB.FLAGC: U30.J4 U56.31 | length 6186.4
  Top Layer w4: v1@6650.14,5781.76 ccw(c6633.92,5797.98) 6656.86,5797.98 ccw(c6679.79,5797.98) v1@6663.57,5781.76 ; v1@6652.97,5778.93 ccw(c6643.58,5788.32) 6656.86,5788.32 ccw(c6670.14,5788.32) v1@6660.75,5778.93 ; v1(6656.86,5775.04) 6656.86,5878.71 6698.58,5920.43 v5(6698.58,5949.34) ; v5@6692.93,5943.68 cw(c6679.27,5930.02) 6698.58,5930.02 cw(c6717.9,5930.03) v5@6704.24,5943.68
  Top Layer w8: U30.J4@7069.06,2120.91 v2(7088.74,2140.59) ; U30.J4@7069.06,2126.75 ccw(c7069.06,2140.85) 7079.03,2130.88 ccw(c7089,2120.91) U30.J4@7074.9,2120.91 ; v2@7079.74,2140.59 cw(c7058.01,2140.59) 7073.38,2125.23 cw(c7088.74,2109.86) v2@7088.74,2131.59
  MidLayer2 w4: v1@6650.14,5768.32 cw(c6633.92,5752.11) 6656.86,5752.11 cw(c6679.79,5752.11) v1@6663.57,5768.32 ; v1@6652.97,5771.15 cw(c6643.58,5761.76) 6656.86,5761.76 cw(c6670.14,5761.76) v1@6660.75,5771.15 ; v1(6656.86,5775.04) 6656.86,5731 6821.48,5566.37 7268.5,5566.37 7576.5,5258.37 7609.84,5258.37 7636.21,5232 8208,5232 8240.19,5199.81 8240.19,4079.77 8130.86,3970.43 8130.86,3529.23 8085,3483.37 7965.19,3483.37 7931.86,3516.71 7873.52,3516.71 7856.86,3500.04 7698.52,3500.04 7565.19,3366.71 7565.19,3001.34 7248.52,2684.67 7248.52,2572.37 7056.86,2380.71 7056.86,2255.04 7030.19,2228.37 7030.19,2170.71 7040.14,2160.76 7068.57,2160.76 v2(7088.74,2140.59)
  Bottom Layer w8: v5@6694.34,5953.58 ccw(c6684.1,5963.82) 6698.58,5963.82 ccw(c6713.07,5963.82) v5@6702.83,5953.58 ; v5(6698.58,5949.34) U56.31@6698.58,5980.67
HOST_USB.FLAGD_CS_N: U30.M1 U56.40 | length 6426
  Top Layer w8: v2@6931.26,2249.7 cw(c6931.26,2227.97) 6946.62,2243.34 cw(c6961.99,2258.7) v2@6940.26,2258.7 ; v2(6931.26,2258.7) U30.M1@6950.94,2239.02 ; U30.M1@6945.1,2239.02 ccw(c6931,2239.02) 6940.97,2248.99 ccw(c6950.94,2258.96) U30.M1@6950.94,2244.86
  MidLayer1 w4: v5@6515.76,6006.34 cw(c6502.1,5992.69) 6521.42,5992.69 cw(c6540.73,5992.69) v5@6527.07,6006.34 ; v5@6523.52,6012 6523.52,6014.71 6521.52,6016.71 6521.42,6016.71 6521.42,5793.81 6956.86,5358.37 7281.86,5358.37 7306.86,5333.37 v1(7329.86,5333.37) ; v1@7323.14,5326.66 ccw(c7306.92,5310.44) 7306.92,5333.37 ccw(c7306.92,5356.31) v1@7323.14,5340.09 ; v1@7325.97,5329.49 ccw(c7316.58,5320.1) 7316.58,5333.37 ccw(c7316.58,5346.65) v1@7325.97,5337.26
  MidLayer2 w4: v1@7054.81,2538.43 ccw(c7038.59,2554.64) 7061.52,2554.64 ccw(c7084.46,2554.64) v1@7068.24,2538.43 ; v1@7057.64,2535.6 ccw(c7048.25,2544.99) 7061.52,2544.99 ccw(c7074.8,2544.99) v1@7065.41,2535.6 ; v1(7061.52,2531.71) 7061.52,2586.33 7115.19,2640 7115.19,2961.35 7440,3286.16 7440,3350 ; v1@7329.86,5323.87 cw(c7329.86,5300.94) 7346.07,5317.16 cw(c7362.29,5333.37) v1@7339.36,5333.37 ; v1@7329.86,5327.87 cw(c7329.86,5314.6) 7339.25,5323.99 cw(c7348.64,5333.37) v1@7335.36,5333.37 ; v1(7329.86,5333.37) 7521.52,5141.71 7628.09,5141.71 7694.38,5208 8198.06,5208 8215.86,5190.2 8215.86,4944.36 8131.86,4860.36 8131.86,4028 8090.19,3986.33 8090.19,3714.34 8034.23,3658.37 7946.23,3658.37 7829.56,3541.71 7805.19,3541.71 7456.86,3541.71 7440.19,3525.04 7440.19,3350
  Bottom Layer w4: v2@6923.48,2266.48 ccw(c6903.26,2286.7) 6931.86,2286.7 ; v2@6926.31,2263.65 ccw(c6912.92,2277.04) 6931.86,2277.04 ; v2(6931.26,2258.7) 6931.86,2258.7 6931.86,2333.37 6940.19,2341.71 6940.19,2410.37 v1(7061.52,2531.71) ; 6931.86,2274.16 ccw(c6946.72,2274.16) v2@6936.21,2263.65 ; 6931.86,2283.82 ccw(c6956.37,2283.82) v2@6939.04,2266.48 ; v1@7052.02,2531.71 cw(c7029.09,2531.71) 7045.31,2515.49 cw(c7061.52,2499.27) v1@7061.52,2522.21 ; v1@7056.02,2531.71 cw(c7042.75,2531.71) 7052.14,2522.32 cw(c7061.52,2512.93) v1@7061.52,2526.21
  Bottom Layer w8: v5@6517.17,6007.76 cw(c6506.93,5997.51) 6521.42,5997.51 cw(c6535.9,5997.51) v5@6525.66,6007.76 ; U56.40@6521.42,5980.67 v5(6521.42,6012)
HOST_USB.IFCLK: R249.1 U30.H2 | length 5283.9
  Top Layer w4: v1(6827.86,6337.37) 6929.19,6337.37 6946.06,6320.5 7033.63,6232.93 7057.86,6208.71 7270.21,6208.71 7315.52,6163.39 7315.52,5606.69 7332.52,5589.69 7332.52,5363.06 7607.19,5088.39 7607.19,4825.06 7638.52,4793.73 7638.52,4396 7598.52,4356 7598.52,4311.37 v1(7580.52,4293.37) ; v1@6831.75,6333.49 cw(c6841.14,6324.1) 6841.14,6337.37 cw(c6841.14,6350.65) v1@6831.75,6341.26 ; v1@6834.57,6330.66 cw(c6850.79,6314.44) 6850.79,6337.37 cw(c6850.79,6360.31) v1@6834.57,6344.09 ; v1@7580.52,4298.87 ccw(c7580.52,4312.15) 7589.91,4302.76 ccw(c7599.3,4293.37) v1@7586.02,4293.37 ; v1@7580.52,4302.87 ccw(c7580.52,4325.81) 7596.74,4309.59 ccw(c7612.96,4293.37) v1@7590.02,4293.37
  Top Layer w8: U30.H2@7108.43,2199.65 v2(7128.11,2219.33) ; U30.H2@7108.43,2205.49 ccw(c7108.43,2219.59) 7118.4,2209.62 ccw(c7128.37,2199.65) U30.H2@7114.27,2199.65 ; v2@7119.11,2219.33 cw(c7097.38,2219.33) 7112.75,2203.97 cw(c7128.11,2188.6) v2@7128.11,2210.33
  MidLayer1 w4: v2@7120.33,2227.11 ccw(c7101.55,2245.89) 7128.11,2245.89 ccw(c7154.67,2245.89) v2@7135.89,2227.11 ; v2@7123.16,2224.28 ccw(c7111.21,2236.23) 7128.11,2236.23 ccw(c7145.01,2236.23) v2@7133.06,2224.28 ; v2(7128.11,2219.33) 7128.11,2271.04 7165.19,2308.12 7165.19,2334.98 7449.19,2618.98 7449.19,2853.69 7506.86,2911.36 7506.86,3313.73 7481.86,3338.73 7481.86,3496.31 7572.29,3586.75 7572.29,4177.81 7594.52,4200.04 7594.52,4279.37 v1(7580.52,4293.37)
  Bottom Layer w4: R249.1@6796.18,6360 6825,6360 6827.86,6357.14 ; R249.1@6799.94,6356.24 cw(c6809.02,6347.16) 6809.02,6360 cw(c6809.02,6372.84) R249.1@6799.94,6363.76 ; R249.1@6802.77,6353.41 cw(c6818.68,6337.5) 6818.68,6360 cw(c6818.68,6382.5) R249.1@6802.77,6366.59 ; v1@6821.92,6344.79 ccw(c6812.04,6357.14) 6827.86,6357.14 ; v1(6827.86,6337.37) 6827.86,6357.14 ; v1@6833.79,6344.79 cw(c6843.67,6357.14) 6827.86,6357.14
HOST_USB.INT_N: R252.1 U30.J6 U56.34 | length 5840.6
  Top Layer w4: v5@6639.53,6004 cw(c6639.53,5984.69) 6653.18,5998.34 cw(c6666.84,6012) v5@6647.53,6012 ; v5(6639.53,6012) 6659.82,5991.71 v1(6948.52,5991.71) ; v1@6941.81,5984.99 ccw(c6925.59,5968.77) 6925.59,5991.71 ccw(c6925.59,6014.64) v1@6941.81,5998.43 ; v1@6944.64,5987.82 ccw(c6935.25,5978.43) 6935.25,5991.71 ccw(c6935.25,6004.99) v1@6944.64,5995.6
  Top Layer w8: U30.J6@7069.06,2042.17 v2(7088.74,2061.85) ; U30.J6@7069.06,2048.01 ccw(c7069.06,2062.11) 7079.03,2052.14 ccw(c7089,2042.17) U30.J6@7074.9,2042.17 ; v2@7079.74,2061.85 cw(c7058.01,2061.85) 7073.38,2046.49 cw(c7088.74,2031.12) v2@7088.74,2052.85
  MidLayer1 w4: v5@6631.53,6012 cw(c6612.21,6012) 6625.87,5998.34 cw(c6639.53,5984.69) v5@6639.53,6004 ; v5@6640.19,6012 6640.19,6016.71 6639.53,6016.71 v5(6639.53,6012) 6600,5972.47 6600,5940.23 6609.83,5930.4 7165.19,5375.04 7481.86,5375.04 7673.52,5183.37 7673.52,4810.75 7615.86,4753.08 7615.86,4589 7490.19,4463.33 7490.19,3853.02 7448.52,3811.35 7448.52,3305.39 7356.52,3213.39 7356.52,2704.67 7366.19,2695 7366.19,2654.02 7162.21,2450.04 7118.52,2450.04 7068.52,2400.04 7068.52,2088.37 7090.19,2066.71 7090.19,2061.85 v2(7088.74,2061.85) ; 7072.33,2084.57 cw(c7049.61,2061.85) v2@7081.74,2061.85 ; 7079.16,2077.74 cw(c7063.27,2061.85) v2@7085.74,2061.85 ; 7080.73,2076.17 ccw(c7088.74,2084.18) v2@7088.74,2072.85
  Bottom Layer w4: v1@6941.81,5998.43 ccw(c6925.59,6014.64) 6948.52,6014.64 ccw(c6971.46,6014.64) v1@6955.24,5998.43 ; v1@6944.64,5995.6 ccw(c6935.25,6004.99) 6948.52,6004.99 ccw(c6961.8,6004.99) v1@6952.41,5995.6 ; v1(6948.52,5991.71) 6948.52,6033.37 7006.86,6091.71 7006.86,6182 6998.86,6190 ; R252.1@6983.82,6190 6998.86,6190 ; R252.1@6992.16,6185.85 cw(c6998.86,6182.53) 6998.86,6190 ; R252.1@6992.16,6194.15 ccw(c6998.86,6197.47) 6998.86,6190
  Bottom Layer w8: v5@6635.28,6007.76 cw(c6625.04,5997.51) 6639.53,5997.51 cw(c6654.01,5997.51) v5@6643.77,6007.76 ; U56.34@6639.53,5980.67 v5(6639.53,6012)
